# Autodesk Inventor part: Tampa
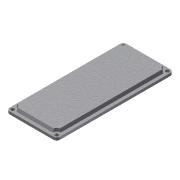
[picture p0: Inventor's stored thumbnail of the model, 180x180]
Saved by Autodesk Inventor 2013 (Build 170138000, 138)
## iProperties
Manager: Alumínio 6061
Created: 2010-06
Part Number: Tampa
Document SubType Name: Modeling
Designer: Usuario
Density: 2.71 g/cm^3
Material: Alumínio 6061
Mass: 65.7837 g
Surface Area: 174.327 cm^2
Volume: 24.2744 cm^3
Author: Usuario
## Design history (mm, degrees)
sketch "Sketch1"
  geometry: L1 (0, 0)-(-56, 0); L2 (-56, 0)-(-56, 130); L3 (-56, 130)-(0, 130); L4 (0, 130)-(0, 0)
  constraints: 8 end point, 2 parallel, 1 horizontal, 1 perpendicular
  dimensions: "d0" = 56 distance of L1.start L1.end; "d1" = 130 distance of L3.end L1.start
extrude "Extrusion1" new body sketch "Sketch1" distance "d2" = 6.5; taper "d3" = 0 deg
fillet "Fillet1" dims "d4" = 3.5
sketch "Sketch3"
  geometry: L1 (-52.5, 65)-(-28, 65); L2 (-28, 65)-(-28, 3.5); L3 (-28, 3.5)-(-48, 3.5); L4 (-52.5, 8)-(-52.5, 65); L5 (-56, 3.5)-(-56, 126.5) reference; L6 (-3.5, 0)-(-52.5, 0) reference; L7 (0, 126.5)-(0, 3.5) reference; L8 (-52.5, 130)-(-3.5, 130) reference; L9 (-52.5, 122)-(-52.5, 65); L10 (-28, 126.5)-(-48, 126.5); L11 (-28, 65)-(-28, 126.5); L12 (-3.5, 65)-(-28, 65); L13 (-3.5, 8)-(-3.5, 65); L14 (-28, 3.5)-(-8, 3.5); L15 (-3.5, 122)-(-3.5, 65); L16 (-28, 126.5)-(-8, 126.5); A1 r 3.5 centre (-3.5, 3.5) between (-3.5, 0) and (0, 3.5) reference; A2 r 0.361 centre (-3.5, 3.5) between (-3.5, 3.139) and (-3.139, 3.5); A3 r 4.5 centre (-52.5, 3.5) between (-48, 3.5) and (-52.5, 8); A4 r 3.5 centre (-52.5, 126.5) between (-52.5, 130) and (-56, 126.5) reference; A5 r 3.5 centre (-52.5, 3.5) between (-56, 3.5) and (-52.5, 0) reference; A6 r 3.5 centre (-3.5, 3.5) between (-3.5, 0) and (0, 3.5) reference; A7 r 3.5 centre (-3.5, 126.5) between (0, 126.5) and (-3.5, 130) reference; A8 r 4.5 centre (-52.5, 126.5) between (-52.5, 122) and (-48, 126.5); A9 r 4.5 centre (-3.5, 3.5) between (-3.5, 8) and (-8, 3.5); A10 r 4.5 centre (-3.5, 126.5) between (-8, 126.5) and (-3.5, 122); 5 further points
  constraints: 24 end point, 15 symmetric about line, 10 point on circle, 5 centre point, 1 perpendicular, 3 other
extrude "Extrusion2" cut sketch "Sketch3" distance "d8" = 3.5; taper "d9" = 0 deg
chamfer "Chamfer1" distance "d10" = 1; stored, may be unused: second distance "d11" = 3.5, angle "d12" = 45 deg
chamfer "Chamfer2" distance "d13" = 1; stored, may be unused: second distance "d14" = 3.5, angle "d15" = 45 deg
chamfer "Chamfer3" distance "d16" = 1; stored, may be unused: second distance "d17" = 3.5, angle "d18" = 45 deg
chamfer "Chamfer4" distance "d19" = 1; stored, may be unused: second distance "d20" = 3.5, angle "d21" = 45 deg
shell "Shell1" dims "d22" = 3
sketch "Sketch4"
  geometry: A1 r 3.5 centre (-52.5, 3.5) between (-56, 3.5) and (-52.5, 0) reference; A2 r 3.5 centre (-3.5, 3.5) between (-3.5, 0) and (0, 3.5) reference; A3 r 3.5 centre (-3.5, 126.5) between (0, 126.5) and (-3.5, 130) reference; A4 r 3.5 centre (-52.5, 126.5) between (-52.5, 130) and (-56, 126.5) reference; 5 further points
  constraints: 4 coincident
hole "Hole1" sketch "Sketch4" diameter "d23" = 4; stored, may be unused: countersink angle "d27" = 90 deg, drill point angle "d29" = 0 deg; dims "d24" = 6, "d25" = 4, "d26" = 2, "d28" = 8
body "Solid1"
node "Projected Loop1"
other parameters: "d5" = 9
